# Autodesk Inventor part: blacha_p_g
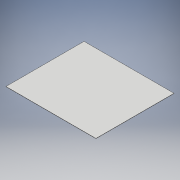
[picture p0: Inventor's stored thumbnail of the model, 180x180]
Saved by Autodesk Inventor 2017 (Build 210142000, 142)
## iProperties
Created: 2020-06
Part Number: blacha_p_g
Material: Generic
Document SubType Name: Modeling
Designer: WindowsX
Density: 1 g/cm^3
Appearance: Default
Author: WindowsX
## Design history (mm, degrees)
sketch "Szkic1"
  geometry: L1 (0, 0)-(1140, 0); L2 (1140, 0)-(1140, 990); L3 (1140, 990)-(0, 990); L4 (0, 990)-(0, 0)
  constraints: 8 end point, 2 parallel, 1 horizontal, 1 perpendicular
  dimensions: "d0" = 1140 distance of L2.end L3.end; "d1" = 990 distance of L1.start L3.end
extrude "Wyciągnięcie proste1" new body sketch "Szkic1" distance "d2" = 3; taper "d3" = 0 deg
node "Bryła1"
